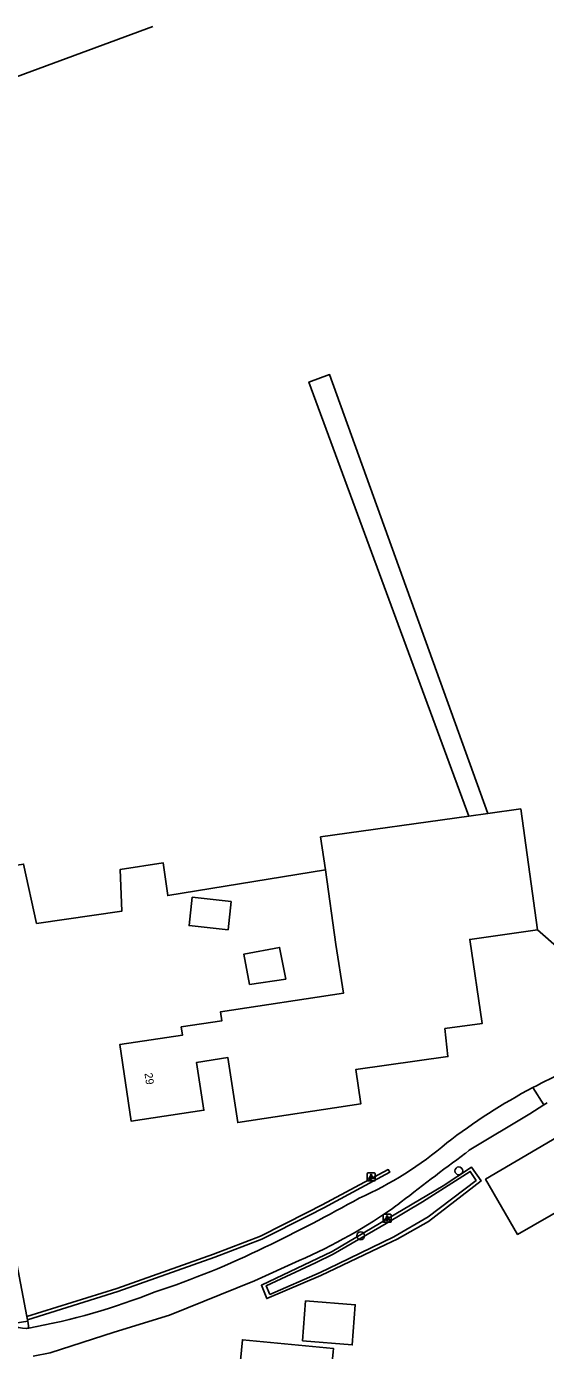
# Model space of a CAD drawing. Extents: x 162515 to 163909, y 388494 to 389773.
# Drawn here: x 162671.5 to 162736.4, y 389592.3 to 389757.7 of the extents above; entities that cross this region are included whole.
import ezdxf

# ---------------------------------------------------------------- set-up
doc = ezdxf.new("R2010")
doc.units = 0
for name, color, linetype in [('IMGEO_Boom', 7, 'Continuous'), ('IMGEO_Erf', 7, 'Continuous'), ('IMGEO_Grasland_agrarisch', 7, 'Continuous'), ('IMGEO_Grasland_overig', 7, 'Continuous'), ('IMGEO_Groenvoorziening', 7, 'Continuous'), ('IMGEO_Haag', 7, 'Continuous'), ('IMGEO_Houtwal', 7, 'Continuous'), ('IMGEO_Lichtpunt', 7, 'Continuous'), ('IMGEO_Open_loods', 7, 'Continuous'), ('IMGEO_Pand', 7, 'Continuous'), ('IMGEO_Pand_nummerreeks', 7, 'Continuous'), ('IMGEO_Rijbaan_lokaal_open', 7, 'Continuous'), ('IMGEO_Waterloop', 7, 'Continuous')]:
    doc.layers.add(name, color=color, linetype=linetype)

msp = doc.modelspace()

# ---------------------------------------------------------------- linework, layer by layer
at = {"layer": 'IMGEO_Boom'}
for centre in [(162725.52, 389614.73), (162713.25, 389606.62)]:
    msp.add_circle(centre, 0.489, dxfattribs=at)
at = {"layer": 'IMGEO_Erf'}
for points in [[(162665.78, 389629.1), (162667.72, 389616.27), (162671.53, 389596.53)], [(162716.4, 389605.53), (162708.26, 389601.65), (162701.52, 389598.78), (162700.85, 389600.44), (162709.68, 389604.64), (162723.55, 389612.84), (162727.1, 389615.21), (162728.3, 389613.48), (162721.73, 389608.4), (162717.83, 389606.21), (162716.4, 389605.53)], [(162671.61, 389596.13), (162671.64, 389595.96)]]:
    msp.add_lwpolyline(points, dxfattribs=at)
at = {"layer": 'IMGEO_Grasland_agrarisch'}
for points in [[(162649.79, 389743.64), (162652.36, 389744.85), (162687.28, 389757.73)], [(162662.11, 389651.63), (162671.12, 389653.06), (162672.75, 389645.66), (162683.4, 389647.17), (162683.2, 389652.4), (162688.55, 389653.24), (162689.14, 389649.13), (162708.84, 389652.34)], [(162735.37, 389644.85), (162740.78, 389640.1), (162744.01, 389639.23), (162762.48, 389644.96), (162786.25, 389652.88), (162786.88, 389653.1), (162790.43, 389644.2)]]:
    msp.add_lwpolyline(points, dxfattribs=at)
at = {"layer": 'IMGEO_Grasland_overig'}
msp.add_lwpolyline([(162736.57, 389623.23), (162736.15, 389622.97)], dxfattribs=at)
msp.add_arc((162770.23, 389558.09), 75.85, 110.9, 117.8602, dxfattribs=at)
at = {"layer": 'IMGEO_Groenvoorziening'}
for points in [[(162671.64, 389595.96), (162670.09, 389595.68), (162669.02, 389596.4), (162664.78, 389619.72), (162663.94, 389628.29)], [(162671.64, 389595.96), (162671.78, 389595.09)]]:
    msp.add_lwpolyline(points, dxfattribs=at)
at = {"layer": 'IMGEO_Haag'}
for points in [[(162671.53, 389596.53), (162682.77, 389600.02), (162694.88, 389604.33), (162700.74, 389606.57), (162706.58, 389609.52), (162708.45, 389610.47), (162716.7, 389614.9), (162716.89, 389614.55), (162708.64, 389610.11), (162706.76, 389609.16), (162700.9, 389606.2), (162695.02, 389603.96), (162682.9, 389599.64), (162671.61, 389596.13)], [(162671.53, 389596.53), (162671.61, 389596.13)]]:
    msp.add_lwpolyline(points, dxfattribs=at)
at = {"layer": 'IMGEO_Houtwal'}
msp.add_lwpolyline([(162726.79, 389659.05), (162706.78, 389713.29), (162709.36, 389714.24), (162729.16, 389659.38)], dxfattribs=at)
at = {"layer": 'IMGEO_Lichtpunt'}
for p, q in [((162714.07, 389614.38), (162714.07, 389613.57)), ((162714.07, 389614.38), (162714.07, 389613.57)), ((162714.97, 389614.47), (162714.17, 389614.47)), ((162714.97, 389614.47), (162714.17, 389614.47)), ((162715.07, 389613.57), (162715.07, 389614.38)), ((162715.07, 389613.57), (162715.07, 389614.38)), ((162714.17, 389613.47), (162714.97, 389613.47)), ((162714.17, 389613.47), (162714.97, 389613.47)), ((162716.07, 389609.21), (162716.07, 389608.4)), ((162716.07, 389609.21), (162716.07, 389608.4)), ((162716.97, 389609.3), (162716.16, 389609.3)), ((162716.97, 389609.3), (162716.16, 389609.3)), ((162717.06, 389608.4), (162717.06, 389609.21)), ((162717.06, 389608.4), (162717.06, 389609.21)), ((162716.16, 389608.31), (162716.97, 389608.31)), ((162716.16, 389608.31), (162716.97, 389608.31))]:
    msp.add_line(p, q, dxfattribs=at)
for points in [[(162714.45, 389614.04), (162714.49, 389614.01), (162714.3, 389613.75), (162714.26, 389613.78), (162714.45, 389614.04)], [(162714.55, 389613.99), (162714.6, 389613.99), (162714.6, 389613.67), (162714.55, 389613.67), (162714.55, 389613.99)], [(162714.66, 389614.01), (162714.7, 389614.04), (162714.88, 389613.78), (162714.85, 389613.75), (162714.66, 389614.01)], [(162716.44, 389608.87), (162716.48, 389608.85), (162716.29, 389608.58), (162716.25, 389608.61), (162716.44, 389608.87)], [(162716.54, 389608.83), (162716.59, 389608.83), (162716.59, 389608.5), (162716.54, 389608.5), (162716.54, 389608.83)], [(162716.65, 389608.85), (162716.69, 389608.87), (162716.88, 389608.61), (162716.84, 389608.58), (162716.65, 389608.85)]]:
    msp.add_lwpolyline(points, dxfattribs=at)
for centre in [(162714.57, 389614.17), (162716.57, 389609.01)]:
    msp.add_circle(centre, 0.0994, dxfattribs=at)
for centre, start, end in [((162714.17, 389614.38), 90, 180), ((162714.17, 389614.38), 90, 180), ((162714.97, 389614.38), 0, 90), ((162714.97, 389614.38), 0, 90), ((162714.17, 389613.57), 180, 270), ((162714.17, 389613.57), 180, 270), ((162714.97, 389613.57), 270, 0), ((162714.97, 389613.57), 270, 360), ((162716.16, 389609.21), 90, 180), ((162716.16, 389609.21), 90, 180), ((162716.97, 389609.21), 0, 90), ((162716.97, 389609.21), 0, 90), ((162716.16, 389608.4), 180, 270), ((162716.16, 389608.4), 180, 270), ((162716.97, 389608.4), 270, 0), ((162716.97, 389608.4), 270, 360)]:
    msp.add_arc(centre, 0.0946, start, end, dxfattribs=at)
at = {"layer": 'IMGEO_Open_loods'}
msp.add_lwpolyline([(162743.22, 389612.74), (162732.87, 389606.78), (162728.87, 389613.69), (162739.13, 389619.73)], dxfattribs=at)
at = {"layer": 'IMGEO_Pand'}
for points in [[(162708.84, 389652.34), (162708.25, 389656.46), (162726.79, 389659.05)], [(162726.79, 389659.05), (162729.16, 389659.38)], [(162729.16, 389659.38), (162733.26, 389659.96), (162735.37, 389644.85)], [(162735.37, 389644.85), (162726.88, 389643.65), (162728.46, 389633.15), (162723.78, 389632.5), (162724.15, 389629.02), (162712.66, 389627.4), (162713.27, 389623.09), (162697.9, 389620.76), (162696.67, 389628.89), (162692.75, 389628.29), (162693.66, 389622.3), (162684.59, 389620.93), (162683.14, 389630.5), (162690.98, 389631.68), (162690.82, 389632.71), (162695.89, 389633.47), (162695.72, 389634.6), (162711.09, 389636.92), (162710.17, 389643.03), (162708.84, 389652.34)], [(162697.08, 389648.4), (162696.69, 389644.85), (162691.81, 389645.38), (162692.2, 389648.93), (162697.08, 389648.4)], [(162703.89, 389638.7), (162699.38, 389638.02), (162698.64, 389641.79), (162703.11, 389642.66), (162703.89, 389638.7)], [(162705.98, 389593.47), (162706.36, 389598.47), (162712.58, 389597.99), (162712.2, 389592.99), (162705.98, 389593.47)], [(162697.73, 389585.85), (162698.48, 389593.62), (162709.84, 389592.54), (162709.8, 389592.12), (162707.49, 389568.04), (162696.13, 389569.12), (162697.17, 389579.98)]]:
    msp.add_lwpolyline(points, dxfattribs=at)
at = {"layer": 'IMGEO_Rijbaan_lokaal_open'}
for points in [[(162734.79, 389625.14), (162736.15, 389622.97)], [(162736.15, 389622.97), (162734.4, 389621.87), (162726.83, 389617.33), (162726.37, 389616.92)], [(162705.55, 389603.52), (162699.99, 389600.99), (162689.36, 389596.71), (162682.45, 389594.59), (162674.43, 389591.99), (162672.34, 389591.57)], [(162671.78, 389595.09), (162671.63, 389595.06), (162671.49, 389595.03)]]:
    msp.add_lwpolyline(points, dxfattribs=at)
for centre, radius, start, end in [((162771.61, 389555.96), 78.38, 118.0273, 127.3996), ((162694.84, 389652.34), 44.89, 293.9708, 310.5304), ((162891.88, 389389.6), 281.19, 126.0578, 128.2489), ((162604.48, 389805.88), 222.82, 295.7482, 299.1694), ((162679.38, 389664.22), 66.1, 293.3237, 305.5321), ((162654.73, 389699.79), 105.43, 288.142, 296.1938), ((162657.31, 389675.46), 81.66, 280.2033, 291.7402), ((162672.43, 389605.3), 10.31, 220.8447, 264.7356)]:
    msp.add_arc(centre, radius, start, end, dxfattribs=at)
at = {"layer": 'IMGEO_Waterloop'}
msp.add_lwpolyline([(162701.92, 389599.3), (162701.45, 389600.37), (162707.61, 389603.22), (162709.83, 389604.3), (162716.43, 389608.15), (162720.97, 389610.87), (162726.95, 389614.67), (162727.67, 389613.54), (162721.68, 389608.97), (162717.41, 389606.49), (162710.46, 389603.11), (162708.18, 389602.01), (162701.92, 389599.3)], dxfattribs=at)

# ---------------------------------------------------------------- texts
at = {"layer": 'IMGEO_Pand_nummerreeks'}
msp.add_text('29', height=1, rotation=278.5773, dxfattribs=at).set_placement((162686.23, 389626.91))

doc.saveas('drawing.dxf')
